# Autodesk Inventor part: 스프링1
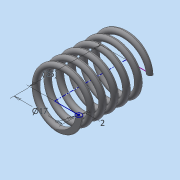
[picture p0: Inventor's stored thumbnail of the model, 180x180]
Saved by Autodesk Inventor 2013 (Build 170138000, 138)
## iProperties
Created: 2019-07
Part Number: 스프링1
Material: 강철, 탄소
Document SubType Name: Modeling
Designer: dgall
Density: 7.87 g/cm^3
Mass: -0.0170894 g
Surface Area: 20.0756 cm^2
Volume: -0.0170894 cm^3
Author: dgall
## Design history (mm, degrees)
sketch "스케치1"
  geometry: L1 (8.5, 0)-(0, 0); L2 (0, 0)-(0, 25.33); L3 (0, 25.33)-(8.5, 25.33); C1 r 1 at (8.5, 0)
  constraints: 6 end point, 2 parallel, 1 centre point, 1 coincident, 1 horizontal, 1 perpendicular
  dimensions: "d0" = 17 diameter of L1.start L2; "d2" = 25.33013 distance of L1.end L2.end (derived); "d3" = 2 diameter of C1
feature "코일1" pitch "d4" = 10; turns "d6" = 6; dims "d5" = 25.33013 (= d2), "d7" = 0, angle "d8" = 90 deg, angle "d9" = 90 deg, "d10" = 0, "d11" = 0
node "작업 평면1"
feature "분할1"
feature "분할2"
node "솔리드1"
